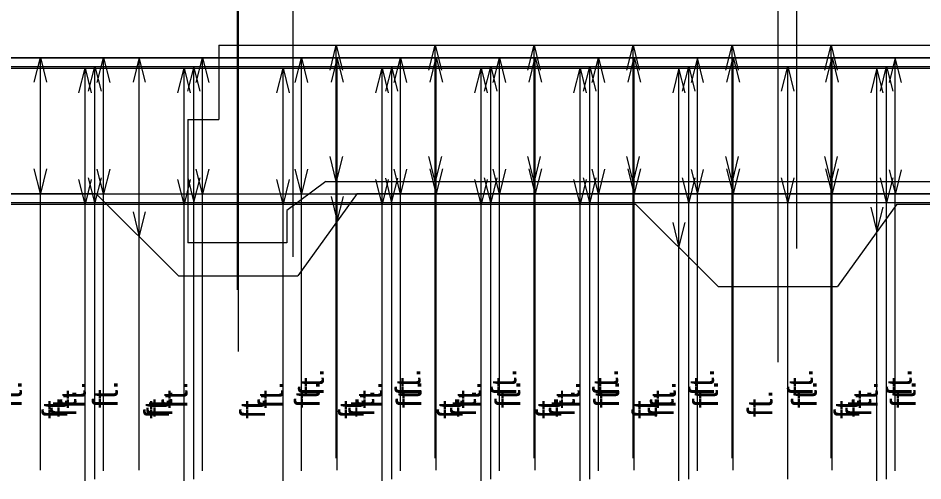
# Model space of a CAD drawing. Extents: x -6.7 to 29.5, y -5.1 to 20.6.
# Drawn here: x 1.15 to 5.72, y 12.449 to 14.787 of the extents above; entities that cross this region are included whole.
import ezdxf

# ---------------------------------------------------------------- set-up
doc = ezdxf.new("R2010")
doc.units = 0
for name, color, linetype in [('Level 5', 7, 'Continuous'), ('Level 6', 7, 'Continuous'), ('Level 7', 7, 'Continuous'), ('Level 8', 7, 'Continuous'), ('Level 9', 7, 'Continuous')]:
    doc.layers.add(name, color=color, linetype=linetype)

msp = doc.modelspace()

# ---------------------------------------------------------------- linework, layer by layer
at = {"layer": 'Level 5'}
for p, q in [((2.2564, 15.9765), (2.2564, 13.4142)), ((2.1636, 14.6495), (7.3436, 14.6495)), ((2.1636, 14.6495), (2.1636, 14.2745)), ((2.7564, 13.962), (2.7564, 14.6495)), ((2.8189, 14.6495), (2.8189, 14.6495)), ((3.2564, 13.962), (3.2564, 14.6495)), ((3.3189, 14.6495), (3.3189, 14.6495)), ((3.7564, 13.962), (3.7564, 14.6495)), ((3.8189, 14.6495), (3.8189, 14.6495)), ((4.2564, 13.962), (4.2564, 14.6495)), ((4.3189, 14.6495), (4.3189, 14.6495)), ((4.7564, 13.962), (4.7564, 14.6495)), ((4.8189, 14.6495), (4.8189, 14.6495)), ((5.2564, 13.962), (5.2564, 14.6495)), ((5.3189, 14.6495), (5.3189, 14.6495)), ((2.0064, 14.2745), (2.1636, 14.2745)), ((2.0064, 14.2745), (2.0064, 13.6518)), ((2.704, 13.962), (2.5064, 13.8153)), ((2.704, 13.962), (6.8033, 13.962)), ((2.7564, 12.5639), (2.7564, 13.962)), ((2.8189, 13.962), (2.8189, 13.962)), ((3.2564, 12.5639), (3.2564, 13.962)), ((3.3189, 13.962), (3.3189, 13.962)), ((3.7564, 12.5639), (3.7564, 13.962)), ((3.8189, 13.962), (3.8189, 13.962)), ((4.2564, 12.5639), (4.2564, 13.962)), ((4.3189, 13.962), (4.3189, 13.962)), ((4.7564, 12.5639), (4.7564, 13.962)), ((4.8189, 13.962), (4.8189, 13.962)), ((5.2564, 12.5639), (5.2564, 13.962)), ((5.3189, 13.962), (5.3189, 13.962)), ((2.5064, 13.8153), (2.5064, 13.6518)), ((2.5064, 13.6518), (2.0064, 13.6518))]:
    msp.add_line(p, q, dxfattribs=at)
for points in [[(2.7252, 14.5245), (2.7564, 14.6495), (2.7877, 14.5245)], [(3.2252, 14.5245), (3.2564, 14.6495), (3.2877, 14.5245)], [(3.7252, 14.5245), (3.7564, 14.6495), (3.7877, 14.5245)], [(4.2252, 14.5245), (4.2564, 14.6495), (4.2877, 14.5245)], [(4.7252, 14.5245), (4.7564, 14.6495), (4.7877, 14.5245)], [(5.2252, 14.5245), (5.2564, 14.6495), (5.2877, 14.5245)], [(2.7877, 14.087), (2.7564, 13.962), (2.7252, 14.087)], [(3.2877, 14.087), (3.2564, 13.962), (3.2252, 14.087)], [(3.7877, 14.087), (3.7564, 13.962), (3.7252, 14.087)], [(4.2877, 14.087), (4.2564, 13.962), (4.2252, 14.087)], [(4.7877, 14.087), (4.7564, 13.962), (4.7252, 14.087)], [(5.2877, 14.087), (5.2564, 13.962), (5.2252, 14.087)]]:
    msp.add_lwpolyline(points, dxfattribs=at)
at = {"layer": 'Level 6'}
for p, q in [((5.081, 15.9069), (5.081, 13.6236)), ((-0.0118, 14.5857), (10.1735, 14.5857)), ((1.581, 13.8982), (1.581, 14.5857)), ((1.6435, 14.5857), (1.6435, 14.5857)), ((2.081, 13.8982), (2.081, 14.5857)), ((2.1435, 14.5857), (2.1435, 14.5857)), ((2.581, 13.8982), (2.581, 14.5857)), ((2.6435, 14.5857), (2.6435, 14.5857)), ((3.081, 13.8982), (3.081, 14.5857)), ((3.1435, 14.5857), (3.1435, 14.5857)), ((3.581, 13.8982), (3.581, 14.5857)), ((3.6435, 14.5857), (3.6435, 14.5857)), ((4.081, 13.7957), (4.081, 14.5857)), ((4.1435, 14.5857), (4.1435, 14.5857)), ((4.5185, 14.5857), (4.5185, 14.5857)), ((4.581, 13.4606), (4.581, 14.5857)), ((4.6435, 14.5857), (4.6435, 14.5857)), ((5.5185, 14.5857), (5.5185, 14.5857)), ((5.581, 13.5917), (5.581, 14.5857)), ((5.6435, 14.5857), (5.6435, 14.5857)), ((0.5286, 13.8982), (5.081, 13.8982)), ((1.581, 12.5001), (1.581, 13.8982)), ((1.6435, 13.8982), (1.6435, 13.8982)), ((2.081, 12.5001), (2.081, 13.8982)), ((2.1435, 13.8982), (2.1435, 13.8982)), ((2.581, 12.5001), (2.581, 13.8982)), ((2.6435, 13.8982), (2.6435, 13.8982)), ((3.081, 12.5001), (3.081, 13.8982)), ((3.1435, 13.8982), (3.1435, 13.8982)), ((3.581, 12.5001), (3.581, 13.8982)), ((3.6435, 13.8982), (3.6435, 13.8982)), ((5.081, 13.8982), (9.6332, 13.8982)), ((4.081, 12.5001), (4.081, 13.7957)), ((5.581, 12.5001), (5.581, 13.5917)), ((4.581, 12.5001), (4.581, 13.4606))]:
    msp.add_line(p, q, dxfattribs=at)
for points in [[(1.5498, 14.4607), (1.581, 14.5857), (1.6123, 14.4607)], [(2.0498, 14.4607), (2.081, 14.5857), (2.1123, 14.4607)], [(2.5498, 14.4607), (2.581, 14.5857), (2.6123, 14.4607)], [(3.0498, 14.4607), (3.081, 14.5857), (3.1123, 14.4607)], [(3.5498, 14.4607), (3.581, 14.5857), (3.6123, 14.4607)], [(4.0498, 14.4607), (4.081, 14.5857), (4.1123, 14.4607)], [(4.6123, 14.4607), (4.581, 14.5857), (4.5498, 14.4607)], [(5.6123, 14.4607), (5.581, 14.5857), (5.5498, 14.4607)], [(1.6123, 14.0232), (1.581, 13.8982), (1.5498, 14.0232)], [(2.1123, 14.0232), (2.081, 13.8982), (2.0498, 14.0232)], [(2.6123, 14.0232), (2.581, 13.8982), (2.5498, 14.0232)], [(3.1123, 14.0232), (3.081, 13.8982), (3.0498, 14.0232)], [(3.6123, 14.0232), (3.581, 13.8982), (3.5498, 14.0232)], [(4.1123, 14.0232), (4.081, 13.8982), (4.0498, 14.0232)], [(4.5498, 14.0218), (4.581, 13.8968), (4.6123, 14.0218)], [(5.5501, 14.0208), (5.5814, 13.8958), (5.6126, 14.0208)]]:
    msp.add_lwpolyline(points, dxfattribs=at)
at = {"layer": 'Level 7'}
for p, q in [((2.5372, 15.8636), (2.5372, 13.5802)), ((-2.5556, 14.5424), (12.6301, 14.5424)), ((1.5372, 13.7524), (1.5372, 14.5424)), ((1.5997, 14.5424), (1.5997, 14.5424)), ((1.9747, 14.5424), (1.9747, 14.5424)), ((2.0372, 13.4173), (2.0372, 14.5424)), ((2.0997, 14.5424), (2.0997, 14.5424)), ((2.9747, 14.5424), (2.9747, 14.5424)), ((3.0372, 13.5484), (3.0372, 14.5424)), ((3.0997, 14.5424), (3.0997, 14.5424)), ((3.5372, 13.8549), (3.5372, 14.5424)), ((3.5997, 14.5424), (3.5997, 14.5424)), ((4.0372, 13.8549), (4.0372, 14.5424)), ((4.0997, 14.5424), (4.0997, 14.5424)), ((4.5372, 13.8549), (4.5372, 14.5424)), ((4.5997, 14.5424), (4.5997, 14.5424)), ((5.0372, 13.8549), (5.0372, 14.5424)), ((5.0997, 14.5424), (5.0997, 14.5424)), ((5.5372, 13.8549), (5.5372, 14.5424)), ((5.5997, 14.5424), (5.5997, 14.5424)), ((-2.0153, 13.8549), (2.5372, 13.8549)), ((2.5372, 13.8549), (7.5372, 13.8549)), ((3.5372, 12.4568), (3.5372, 13.8549)), ((3.5997, 13.8549), (3.5997, 13.8549)), ((4.0372, 12.4568), (4.0372, 13.8549)), ((4.0997, 13.8549), (4.0997, 13.8549)), ((4.5372, 12.4568), (4.5372, 13.8549)), ((4.5997, 13.8549), (4.5997, 13.8549)), ((5.0372, 12.4568), (5.0372, 13.8549)), ((5.0997, 13.8549), (5.0997, 13.8549)), ((5.5372, 12.4568), (5.5372, 13.8549)), ((5.5997, 13.8549), (5.5997, 13.8549)), ((1.5372, 12.4568), (1.5372, 13.7524)), ((3.0372, 12.4568), (3.0372, 13.5484)), ((2.0372, 12.4568), (2.0372, 13.4173))]:
    msp.add_line(p, q, dxfattribs=at)
for points in [[(1.506, 14.4174), (1.5372, 14.5424), (1.5685, 14.4174)], [(2.0685, 14.4174), (2.0372, 14.5424), (2.006, 14.4174)], [(3.0685, 14.4174), (3.0372, 14.5424), (3.006, 14.4174)], [(3.506, 14.4174), (3.5372, 14.5424), (3.5685, 14.4174)], [(4.006, 14.4174), (4.0372, 14.5424), (4.0685, 14.4174)], [(4.506, 14.4174), (4.5372, 14.5424), (4.5685, 14.4174)], [(5.006, 14.4174), (5.0372, 14.5424), (5.0685, 14.4174)], [(5.506, 14.4174), (5.5372, 14.5424), (5.5685, 14.4174)], [(1.5685, 13.9799), (1.5372, 13.8549), (1.506, 13.9799)], [(2.0064, 13.9798), (2.0376, 13.8548), (2.0689, 13.9798)], [(3.0052, 13.9784), (3.0365, 13.8534), (3.0677, 13.9784)], [(3.5685, 13.9799), (3.5372, 13.8549), (3.506, 13.9799)], [(4.0685, 13.9799), (4.0372, 13.8549), (4.006, 13.9799)], [(4.5685, 13.9799), (4.5372, 13.8549), (4.506, 13.9799)], [(5.0685, 13.9799), (5.0372, 13.8549), (5.006, 13.9799)], [(5.5685, 13.9799), (5.5372, 13.8549), (5.506, 13.9799)]]:
    msp.add_lwpolyline(points, dxfattribs=at)
at = {"layer": 'Level 8'}
for p, q in [((4.9882, 15.8553), (4.9882, 13.0488)), ((-0.1047, 14.5341), (10.0808, 14.5341)), ((1.4882, 13.8466), (1.4882, 14.5341)), ((1.5507, 14.5341), (1.5507, 14.5341)), ((1.9882, 13.8466), (1.9882, 14.5341)), ((2.0507, 14.5341), (2.0507, 14.5341)), ((2.4882, 13.8466), (2.4882, 14.5341)), ((2.5507, 14.5341), (2.5507, 14.5341)), ((2.9882, 13.8466), (2.9882, 14.5341)), ((3.0507, 14.5341), (3.0507, 14.5341)), ((3.4882, 13.8466), (3.4882, 14.5341)), ((3.5507, 14.5341), (3.5507, 14.5341)), ((3.9882, 13.7441), (3.9882, 14.5341)), ((4.0507, 14.5341), (4.0507, 14.5341)), ((4.4257, 14.5341), (4.4257, 14.5341)), ((4.4882, 13.409), (4.4882, 14.5341)), ((4.5507, 14.5341), (4.5507, 14.5341)), ((5.4257, 14.5341), (5.4257, 14.5341)), ((5.4882, 13.54), (5.4882, 14.5341)), ((5.5507, 14.5341), (5.5507, 14.5341)), ((0.4357, 13.8466), (4.2688, 13.8466)), ((1.4882, 12.4485), (1.4882, 13.8466)), ((1.5507, 13.8466), (1.5507, 13.8466)), ((1.9882, 12.4485), (1.9882, 13.8466)), ((2.0507, 13.8466), (2.0507, 13.8466)), ((2.4882, 12.4485), (2.4882, 13.8466)), ((2.5507, 13.8466), (2.5507, 13.8466)), ((2.9882, 12.4485), (2.9882, 13.8466)), ((3.0507, 13.8466), (3.0507, 13.8466)), ((3.4882, 12.4485), (3.4882, 13.8466)), ((3.5507, 13.8466), (3.5507, 13.8466)), ((4.2688, 13.8466), (4.6868, 13.4309)), ((5.5887, 13.8466), (5.2895, 13.4309)), ((5.5887, 13.8466), (9.5404, 13.8466)), ((3.9882, 12.4485), (3.9882, 13.7441)), ((5.4882, 12.4485), (5.4882, 13.54)), ((4.4882, 12.4485), (4.4882, 13.409)), ((4.6868, 13.4309), (5.2895, 13.4309))]:
    msp.add_line(p, q, dxfattribs=at)
for points in [[(1.4569, 14.4091), (1.4882, 14.5341), (1.5194, 14.4091)], [(1.9569, 14.4091), (1.9882, 14.5341), (2.0194, 14.4091)], [(2.4569, 14.4091), (2.4882, 14.5341), (2.5194, 14.4091)], [(2.9569, 14.4091), (2.9882, 14.5341), (3.0194, 14.4091)], [(3.4569, 14.4091), (3.4882, 14.5341), (3.5194, 14.4091)], [(3.9569, 14.4091), (3.9882, 14.5341), (4.0194, 14.4091)], [(4.5194, 14.4091), (4.4882, 14.5341), (4.4569, 14.4091)], [(5.5194, 14.4091), (5.4882, 14.5341), (5.4569, 14.4091)], [(1.5194, 13.9716), (1.4882, 13.8466), (1.4569, 13.9716)], [(2.0194, 13.9716), (1.9882, 13.8466), (1.9569, 13.9716)], [(2.5194, 13.9716), (2.4882, 13.8466), (2.4569, 13.9716)], [(3.0194, 13.9716), (2.9882, 13.8466), (2.9569, 13.9716)], [(3.5194, 13.9716), (3.4882, 13.8466), (3.4569, 13.9716)], [(4.0194, 13.9716), (3.9882, 13.8466), (3.9569, 13.9716)], [(5.4569, 13.8319), (5.4882, 13.7069), (5.5194, 13.8319)], [(4.4569, 13.7534), (4.4882, 13.6284), (4.5194, 13.7534)]]:
    msp.add_lwpolyline(points, dxfattribs=at)
at = {"layer": 'Level 9'}
for p, q in [((2.2619, 15.9094), (2.2619, 13.1029)), ((-2.831, 14.5882), (12.3547, 14.5882)), ((1.2619, 13.7982), (1.2619, 14.5882)), ((1.3244, 14.5882), (1.3244, 14.5882)), ((1.6994, 14.5882), (1.6994, 14.5882)), ((1.7619, 13.4631), (1.7619, 14.5882)), ((1.8244, 14.5882), (1.8244, 14.5882)), ((2.6994, 14.5882), (2.6994, 14.5882)), ((2.7619, 13.5942), (2.7619, 14.5882)), ((2.8244, 14.5882), (2.8244, 14.5882)), ((3.2619, 13.9007), (3.2619, 14.5882)), ((3.3244, 14.5882), (3.3244, 14.5882)), ((3.7619, 13.9007), (3.7619, 14.5882)), ((3.8244, 14.5882), (3.8244, 14.5882)), ((4.2619, 13.9007), (4.2619, 14.5882)), ((4.3244, 14.5882), (4.3244, 14.5882)), ((4.7619, 13.9007), (4.7619, 14.5882)), ((4.8244, 14.5882), (4.8244, 14.5882)), ((5.2619, 13.9007), (5.2619, 14.5882)), ((5.3244, 14.5882), (5.3244, 14.5882)), ((-2.2906, 13.9007), (1.5425, 13.9007)), ((1.5425, 13.9007), (1.9605, 13.485)), ((2.8624, 13.9007), (2.5632, 13.485)), ((2.8624, 13.9007), (6.6614, 13.9007)), ((3.2619, 12.5026), (3.2619, 13.9007)), ((3.3244, 13.9007), (3.3244, 13.9007)), ((3.7619, 12.5026), (3.7619, 13.9007)), ((3.8244, 13.9007), (3.8244, 13.9007)), ((4.2619, 12.5026), (4.2619, 13.9007)), ((4.3244, 13.9007), (4.3244, 13.9007)), ((4.7619, 12.5026), (4.7619, 13.9007)), ((4.8244, 13.9007), (4.8244, 13.9007)), ((5.2619, 12.5026), (5.2619, 13.9007)), ((5.3244, 13.9007), (5.3244, 13.9007)), ((1.2619, 12.5026), (1.2619, 13.7982)), ((2.7619, 12.5026), (2.7619, 13.5942)), ((1.9605, 13.485), (2.5632, 13.485)), ((1.7619, 12.5026), (1.7619, 13.4631))]:
    msp.add_line(p, q, dxfattribs=at)
for points in [[(1.2306, 14.4632), (1.2619, 14.5882), (1.2931, 14.4632)], [(1.7931, 14.4632), (1.7619, 14.5882), (1.7306, 14.4632)], [(2.7931, 14.4632), (2.7619, 14.5882), (2.7306, 14.4632)], [(3.2306, 14.4632), (3.2619, 14.5882), (3.2931, 14.4632)], [(3.7306, 14.4632), (3.7619, 14.5882), (3.7931, 14.4632)], [(4.2306, 14.4632), (4.2619, 14.5882), (4.2931, 14.4632)], [(4.7306, 14.4632), (4.7619, 14.5882), (4.7931, 14.4632)], [(5.2306, 14.4632), (5.2619, 14.5882), (5.2931, 14.4632)], [(1.2931, 14.0257), (1.2619, 13.9007), (1.2306, 14.0257)], [(3.2931, 14.0257), (3.2619, 13.9007), (3.2306, 14.0257)], [(3.7931, 14.0257), (3.7619, 13.9007), (3.7306, 14.0257)], [(4.2931, 14.0257), (4.2619, 13.9007), (4.2306, 14.0257)], [(4.7931, 14.0257), (4.7619, 13.9007), (4.7306, 14.0257)], [(5.2931, 14.0257), (5.2619, 13.9007), (5.2306, 14.0257)], [(2.7306, 13.886), (2.7619, 13.761), (2.7931, 13.886)], [(1.7306, 13.8075), (1.7619, 13.6825), (1.7931, 13.8075)]]:
    msp.add_lwpolyline(points, dxfattribs=at)

# ---------------------------------------------------------------- texts
at = {"layer": 'Level 5'}
for p in [(2.6939, 12.646), (3.182, 12.646), (3.6666, 12.646), (4.1805, 12.646), (4.665, 12.646), (5.1643, 12.646), (5.6635, 12.646)]:
    msp.add_text('     ft.', height=0.125, rotation=90, dxfattribs=at).set_placement(p)
at = {"layer": 'Level 6'}
for p in [(1.4911, 12.5822), (2.0051, 12.5822), (2.4896, 12.5822), (2.9889, 12.5822), (3.4881, 12.5822), (3.9874, 12.5822), (4.4719, 12.5822), (5.4922, 12.5822)]:
    msp.add_text('     ft.', height=0.125, rotation=90, dxfattribs=at).set_placement(p)
at = {"layer": 'Level 7'}
for p in [(1.4436, 12.5389), (1.9281, 12.5389), (2.9484, 12.5389), (3.4624, 12.5389), (3.9616, 12.5389), (4.4609, 12.5389), (4.9601, 12.5389), (5.4593, 12.5389)]:
    msp.add_text('     ft.', height=0.125, rotation=90, dxfattribs=at).set_placement(p)
at = {"layer": 'Level 8'}
for p in [(1.3983, 12.5306), (1.9122, 12.5306), (2.3968, 12.5306), (2.896, 12.5306), (3.3952, 12.5306), (3.8945, 12.5306), (4.379, 12.5306), (5.3994, 12.5306)]:
    msp.add_text('     ft.', height=0.125, rotation=90, dxfattribs=at).set_placement(p)
at = {"layer": 'Level 9'}
for p in [(1.1682, 12.5847), (1.6527, 12.5847), (2.6731, 12.5847), (3.187, 12.5847), (3.6862, 12.5847), (4.1855, 12.5847), (4.6847, 12.5847), (5.184, 12.5847), (5.6832, 12.5847)]:
    msp.add_text('     ft.', height=0.125, rotation=90, dxfattribs=at).set_placement(p)

doc.saveas('drawing.dxf')
